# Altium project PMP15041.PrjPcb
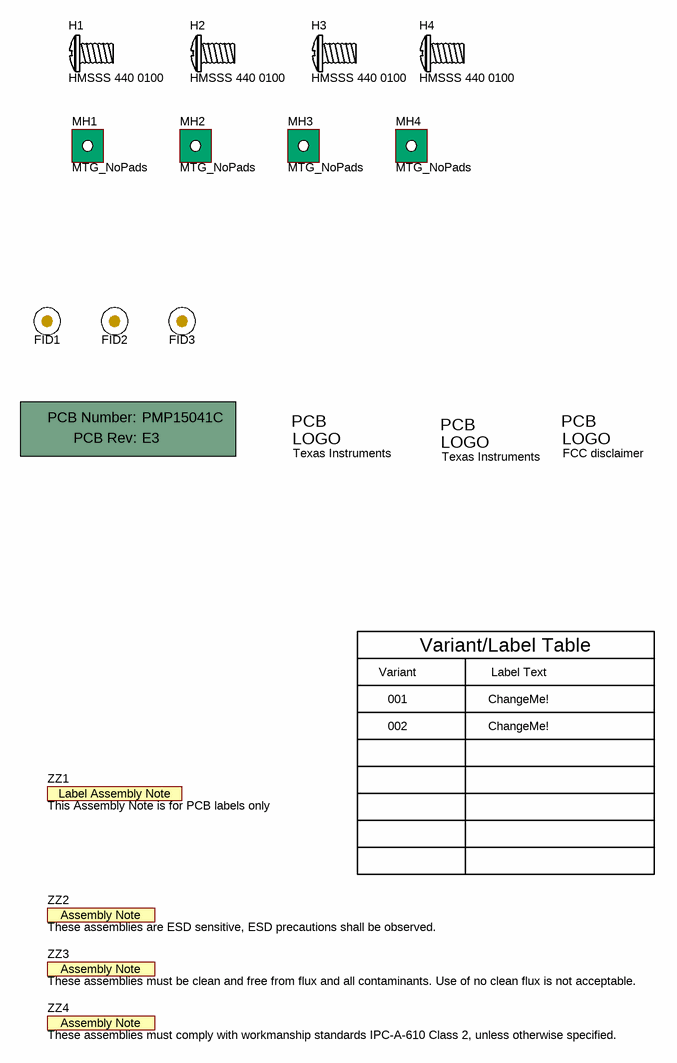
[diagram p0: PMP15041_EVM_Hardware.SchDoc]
CopyrightYear: 2017; PCB_Layout: K Nielson; PCB_Rev: E3; PRJ_Customer: Public Release; PRJ_Engineer: G Roecker; PRJ_Number: PMP15041C; PRJ_Title: LM5150/LM5141 APEC Demo; SCH_Rev: E3; TechSupport: http://www.ti.com/support; TID: N/A
4 sheets, 129 parts. Net scope: global (net labels, ports and power ports of the same name join across sheets).
Board file: PMP15041_EVM_PCB.PcbDoc
Sheets:
  PMP15041_EVM_Hardware.SchDoc
  PMP15041_EVM_Boost_Stage.SchDoc
  PMP15041_EVM_Buck_Stage.SchDoc
  PMP15041_SYNC_Stage.SchDoc

## Sheet PMP15041_EVM_Hardware.SchDoc
size 431 x 279 mm; Date: Not shown in title block; ApprovedBy: Not shown in title block; CheckedBy: Not shown in title block; Author: Not shown in title block; CompanyName: Not shown in title block; Engineer: Not shown in title block; Organization: Not shown in title block; Address1: Not shown in title block; Address2: Not shown in title block; Address3: Not shown in title block; Address4: Not shown in title block; DocumentNumber: 2; Revision: Use project parameter SCH_Rev; SheetNumber: 2; SheetTotal: 5; PageSetup: Record=PageOptions¦CenterHorizontal=True¦CenterVertical=True¦PrintScale=1.00¦XCorrection=1.00¦YCorrection=1.00¦PrintKind=0¦BorderSize=5000000¦LeftOffset=0¦BottomOffset=0¦Orientation=2¦PaperLength=1000¦PaperWidth=1000¦Scale=100¦PaperSource=15¦PrintQuality=600¦MediaType=1¦DitherType=10¦PaperKind=Letter¦PrintScaleMode=1

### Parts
!PCB1  Printed Circuit Board  (value not drawn)  (mechanical)
FID1  Fiducial  [Fiducial10-20]  (value not drawn)
FID2  Fiducial  [Fiducial10-20]  (value not drawn)
FID3  Fiducial  [Fiducial10-20]  (value not drawn)
H1  HMSSS 440 0100  (mechanical)
H2  HMSSS 440 0100  (mechanical)
H3  HMSSS 440 0100  (mechanical)
H4  HMSSS 440 0100  (mechanical)
Logo1  Texas Instruments  [TI_Stacked_Overlay_Small]  (no BOM)
Logo2  Texas Instruments  [TI_Symbol_Overlay_Medium]  (no BOM)
Logo3  FCC disclaimer  [FCC_disclaimer_stacked]  (no BOM)
MH1  MTG_NoPads  [MTG_159mil]  (no BOM)
MH2  MTG_NoPads  [MTG_159mil]  (no BOM)
MH3  MTG_NoPads  [MTG_159mil]  (no BOM)
MH4  MTG_NoPads  [MTG_159mil]  (no BOM)
ZZ1  This Assembly Note is for PCB labels only  [AssemblyNoteLabel]  (no BOM)
ZZ2  These assemblies are ESD sensitive, ESD precautions shall be observed.  [AssemblyNote]  (no BOM)
ZZ3  These assemblies must be clean and free from flux and all contaminants. Use of no clean flux is not acceptable.  [AssemblyNote]  (no BOM)
ZZ4  These assemblies must comply with workmanship standards IPC-A-610 Class 2, unless otherwise specified.  [AssemblyNote]  (no BOM)

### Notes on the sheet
- Variant
- Variant/Label Table
- Label Text
- 001
- 002
- ChangeMe!

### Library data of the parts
!PCB1 = CMP-0003618-2: Manufacturer: Any; PartNumber: PMP15041C
FID1-FID3 = CMP-0077181-1: Fiducial mark.  There is nothing to buy or mount.
H1-H4 = CMP-0003896-1: MACHINE SCREW HEX 4-40; Manufacturer: B&F Fastener Supply; CompType: Hardware
Logo1 = CMP-0074838-1: Texas Instrument Corporate Signature; SymbolCreator: a0412235; Lib Reference: TI_Logo; Library Reference: Logo
Logo2 = CMP-0074838-1: Texas Instrument Corporate Signature; Library Reference: Logo; SymbolCreator: a0412235; Lib Reference: TI_Logo
Logo3 = CMP-0074847-1: FCC_disclaimer; Library Reference: Logo
MH1-MH4 = CMP-0078424-2: PCB Mounting Hole, No Pad; Manufacturer: Any; Key: Mounting Hole (non-standard) No Pad
ZZ1 = CMP-0003616-3
ZZ2 = CMP-0077236-1
ZZ3 = CMP-0077237-1
ZZ4 = CMP-0077238-1

## Sheet PMP15041_EVM_Boost_Stage.SchDoc
size 431 x 279 mm; Date: Not shown in title block; ApprovedBy: Not shown in title block; CheckedBy: Not shown in title block; Author: Not shown in title block; CompanyName: Not shown in title block; Engineer: Not shown in title block; Organization: Not shown in title block; Address1: Not shown in title block; Address2: Not shown in title block; Address3: Not shown in title block; Address4: Not shown in title block; DocumentNumber: 3; Revision: Use project parameter SCH_Rev; SheetNumber: 3; SheetTotal: 5; PageSetup: Record=PageOptions¦CenterHorizontal=True¦CenterVertical=True¦PrintScale=1.00¦XCorrection=1.00¦YCorrection=1.00¦PrintKind=0¦BorderSize=5000000¦LeftOffset=0¦BottomOffset=0¦Orientation=2¦PaperLength=1000¦PaperWidth=1000¦Scale=100¦PaperSource=15¦PrintQuality=600¦MediaType=1¦DitherType=10¦PaperKind=Letter¦PrintScaleMode=1
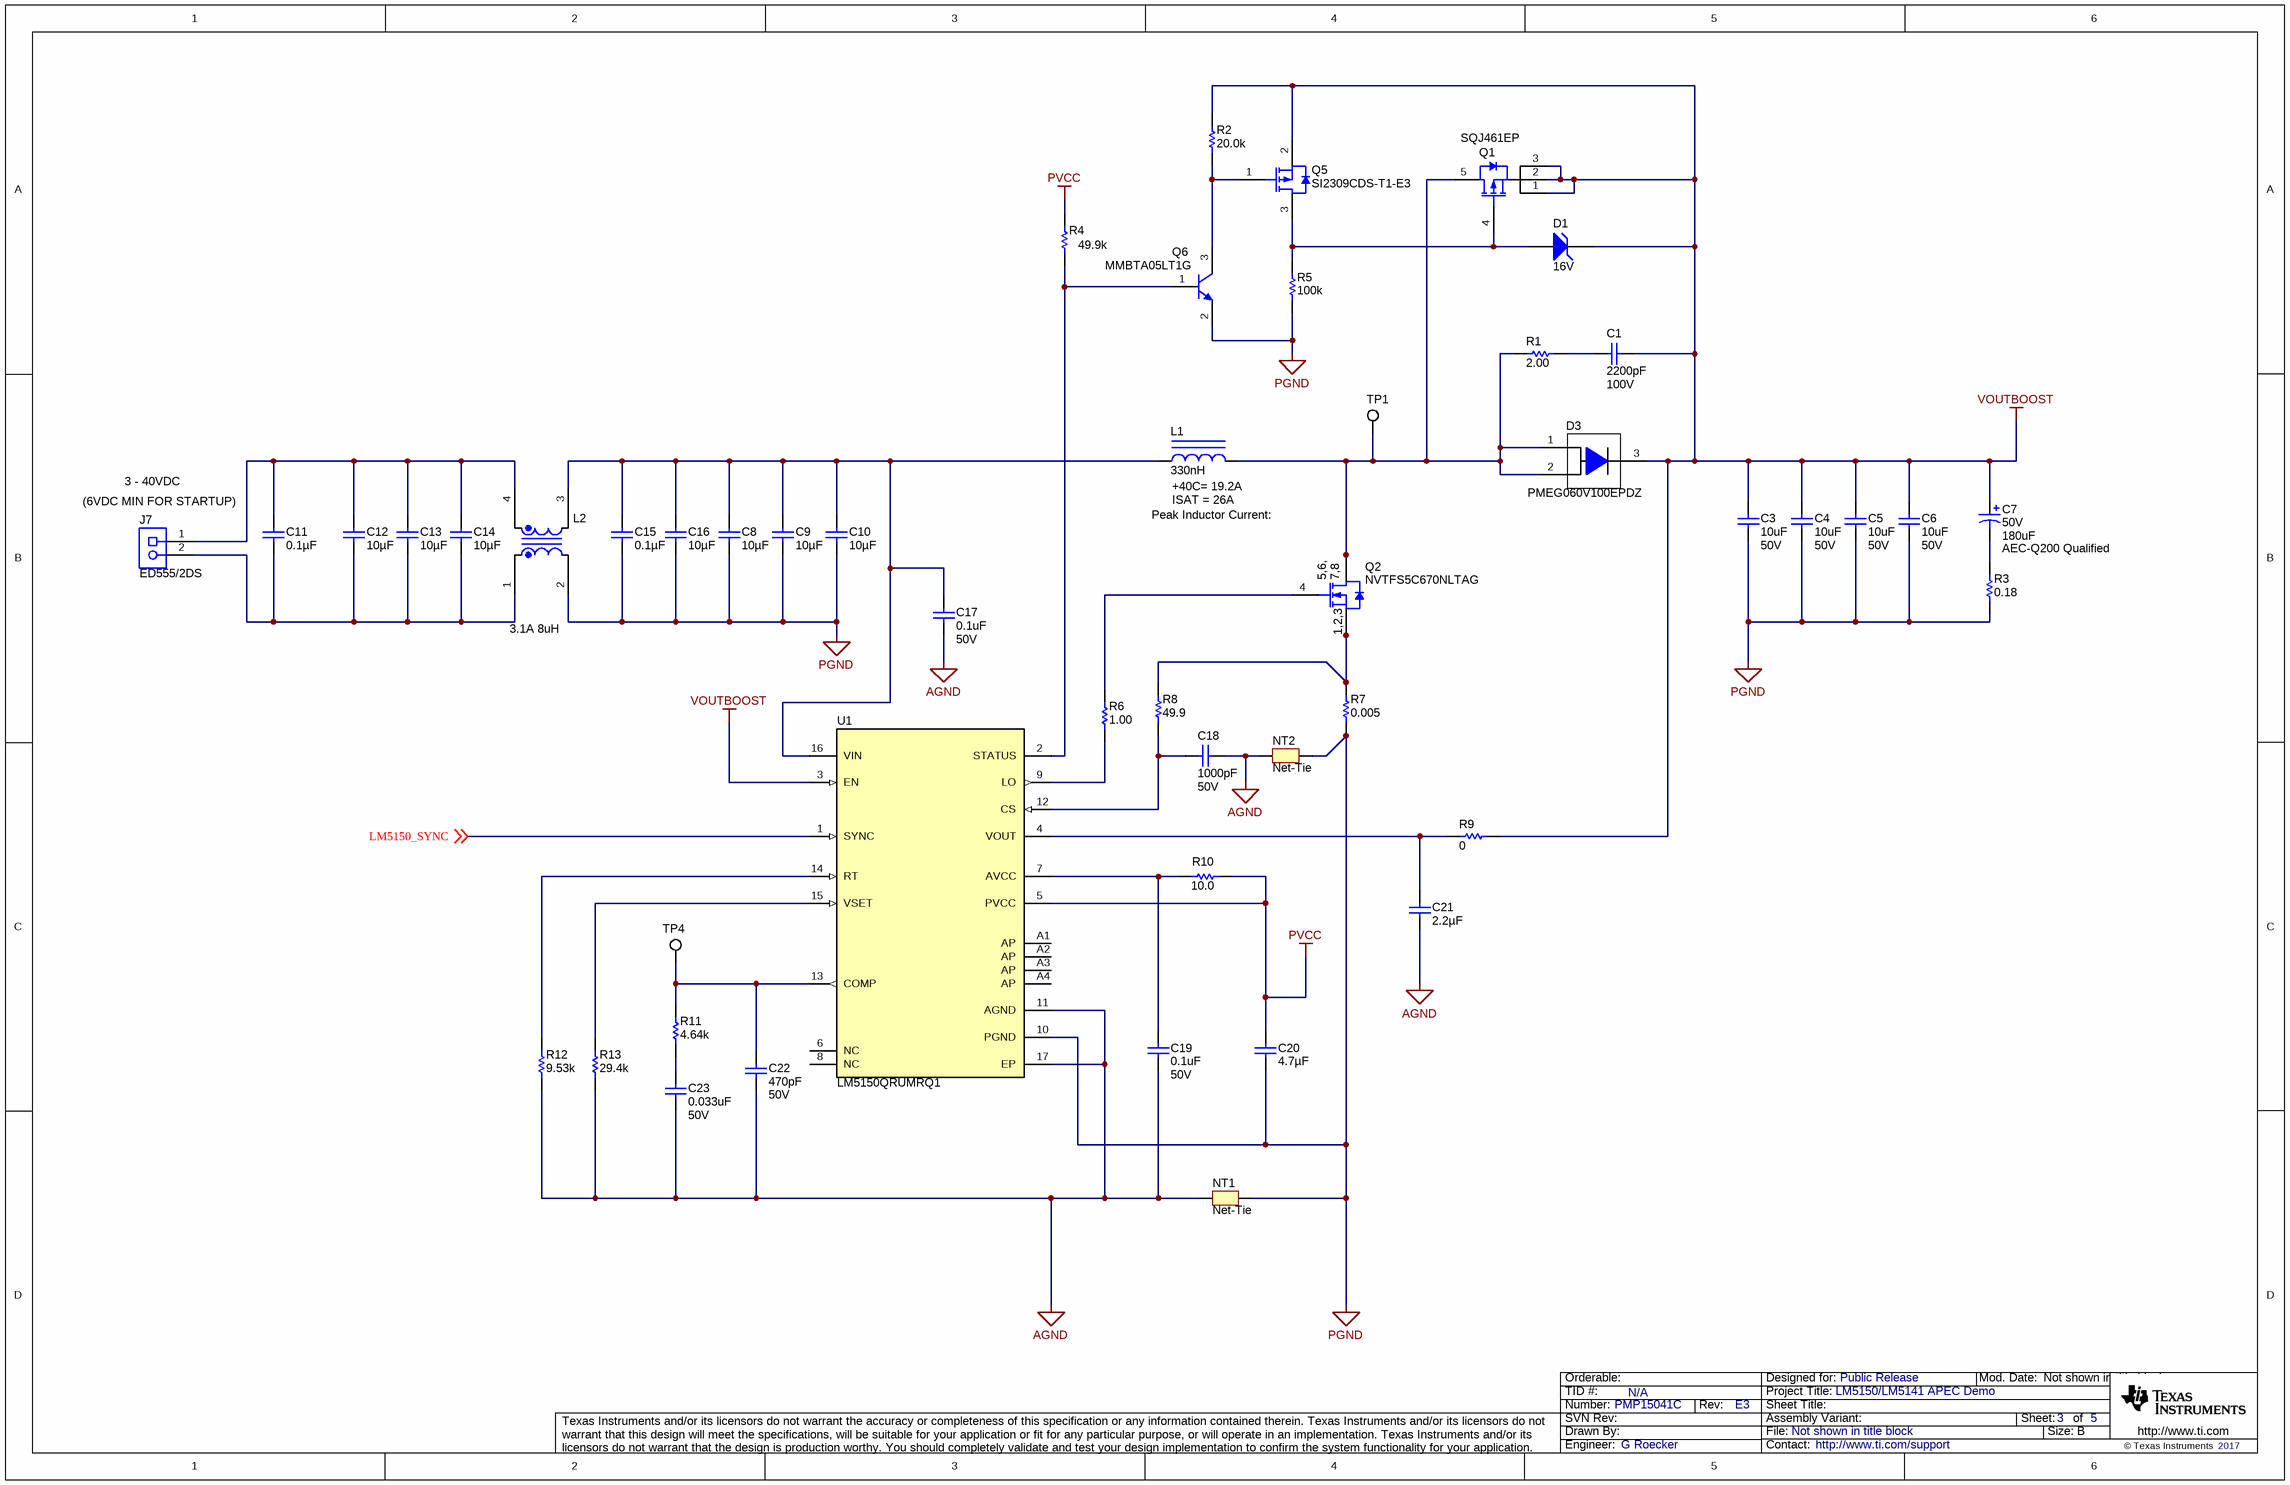
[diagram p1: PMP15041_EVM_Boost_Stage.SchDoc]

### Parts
C1  ValueDisplayed: 2200pF  VDC_V: 100V  [0603L]  (hidden comment: GRM188R72A222KA01D)
C3  ValueDisplayed: 10uF  VDC_V: 50V  [1210_280]  (hidden comment: CGA6P3X7S1H106K250AB)
C4  ValueDisplayed: 10uF  VDC_V: 50V  [1210_280]  (hidden comment: CGA6P3X7S1H106K250AB)
C5  ValueDisplayed: 10uF  VDC_V: 50V  [1210_280]  (hidden comment: CGA6P3X7S1H106K250AB)
C6  ValueDisplayed: 10uF  VDC_V: 50V  [1210_280]  (hidden comment: CGA6P3X7S1H106K250AB)
C7  VDC_V: 50V  ValueDisplayed: 180uF  [CR_1000x1270]  (hidden comment: PCR1H181MCL1GS)
C8  ValueDisplayed: 10µF  [1210_280]  (hidden comment: GRM32ER71H106KA12L)
C9  ValueDisplayed: 10µF  [1210_280]  (hidden comment: GRM32ER71H106KA12L)
C10  ValueDisplayed: 10µF  [1210_280]  (hidden comment: GRM32ER71H106KA12L)
C11  ValueDisplayed: 0.1µF  [0805_HV]  (hidden comment: C0805C104K1RACTU)
C12  ValueDisplayed: 10µF  [1210_280]  (hidden comment: C3225X7R1H106M250AC)
C13  ValueDisplayed: 10µF  [1210_280]  (hidden comment: C3225X7R1H106M250AC)
C14  ValueDisplayed: 10µF  [1210_280]  (hidden comment: C3225X7R1H106M250AC)
C15  ValueDisplayed: 0.1µF  [0805_HV]  (hidden comment: C0805C104K1RACTU)
C16  ValueDisplayed: 10µF  [1210_280]  (hidden comment: C3225X7R1H106M250AC)
C17  ValueDisplayed: 0.1uF  VDC_V: 50V  [0402L]  (hidden comment: CGA2B3X7R1H104M050BB)
C18  ValueDisplayed: 1000pF  VDC_V: 50V  [0402L]  (hidden comment: CGA2B2C0G1H102J050BA)
C19  ValueDisplayed: 0.1uF  VDC_V: 50V  [0402L]  (hidden comment: GCM155R71H104KE02D)
C20  ValueDisplayed: 4.7µF  [0805_HV1]  (hidden comment: GRM21BR71C475KA73L)
C21  ValueDisplayed: 2.2µF  [0805_HV1]  (hidden comment: C2012X7R1H225K125AC)
C22  ValueDisplayed: 470pF  VDC_V: 50V  [0402L]  (hidden comment: GCM155R71H471KA37D)
C23  ValueDisplayed: 0.033uF  VDC_V: 50V  [0402L]  (hidden comment: CGA2B3X7R1H333K050BB)
D1  value 16V  [SOD-123]  (hidden comment: DDZ16Q-7)
D3  PMEG060V100EPDZ  [SOT1289]
J7  ED555/2DS  [TERM_BLK_ED555-2DS]
L1  Isat: ISAT = 26A  Imax_A: +40C= 19.2A  ValueDisplayed: 330nH  [XAL5030]  (hidden comment: XAL5030-331MEB)
L2  PLT5BPH5013R1SNL  [PLT5BPH_SN]  (value not drawn)
NT1  Net-Tie  [Net-Tie_10mil]  (net tie, no BOM)
NT2  Net-Tie  [Net-Tie_10mil]  (net tie, no BOM)
Q1  SQJ461EP  [PowerPAK_SO-8L]
Q2  NVTFS5C670NLTAG  [Power_WDFN-8]
Q5  SI2309CDS-T1-E3  [SOT-23]
Q6  MMBTA05LT1G  [SOT-23]
R1  ValueDisplayed: 2.00  [1210M]  (hidden comment: ERJ-14BQF2R0U)
R2  ValueDisplayed: 20.0k  [0603L]  (hidden comment: CRCW060320K0FKEA)
R3  ValueDisplayed: 0.18  [1206]  (hidden comment: ERJ-8RSJR18V)
R4  ValueDisplayed: 49.9k  [0603L]  (hidden comment: CRCW060349K9FKEA)
R5  ValueDisplayed: 100k  [0603L]  (hidden comment: CRCW0603100KFKEA)
R6  ValueDisplayed: 1.00  [0402L]  (hidden comment: CRCW04021R00FKED)
R7  ValueDisplayed: 0.005  [KRL2012]  (hidden comment: KRL2012M-R005-F-T1)
R8  ValueDisplayed: 49.9  [0402L]  (hidden comment: CRCW040249R9FKED)
R9  ValueDisplayed: 0  [0402L]  (hidden comment: MCR01MZPJ000)
R10  ValueDisplayed: 10.0  [0402L]  (hidden comment: RMCF0402JT10R0)
R11  ValueDisplayed: 4.64k  [0402L]  (hidden comment: CRCW04024K64FKED)
R12  ValueDisplayed: 9.53k  [0402L]  (hidden comment: CRCW04029K53FKED)
R13  ValueDisplayed: 29.4k  [0402L]  (hidden comment: CRCW040229K4FKED)
TP1  5015  [Testpoint_Keystone_Miniature]  (value not drawn)
TP4  5002  [Keystone5002]  (value not drawn)
U1  LM5150QRUMRQ1  [RUM0016C]

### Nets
AGND: C17.2 C18.2 C19.1 C21.1 C22.2 C23.2 NT1.1 NT2.1 R12.1 R13.1 U1.11(AGND) U1.17(EP)
PGND: C3.2 C4.2 C5.2 C6.2 C8.2 C9.2 C10.2 C15.2 C16.2 C20.2 L2.2 NT1.2 NT2.2 Q6.2(E) R3.1 R5.1 R7.1 U1.10(PGND)
PVCC: C20.1 R4.2 R10.2 U1.5(PVCC)
VOUTBOOST: C1.1 C3.1 C4.1 C5.1 C6.1 C7.1(+) D1.1(K) D3.3(K) Q1.1(S) Q1.2(S) Q1.3(S) Q5.2(S) R2.2 R9.1 U1.3(EN)
LM5150_SYNC: U1.1(SYNC) ; off-sheet LM5150_SYNC
NetC1_2: C1.2 R1.2
NetC7_2: C7.2(-) R3.2
NetC8_1: C8.1 C9.1 C10.1 C15.1 C16.1 C17.1 L1.1 L2.3 U1.16(VIN)
NetC11_1: C11.1 C12.1 C13.1 C14.1 J7.1 L2.4
NetC11_2: C11.2 C12.2 C13.2 C14.2 J7.2 L2.1
NetC18_1: C18.1 R8.1 U1.12(CS)
NetC19_2: C19.2 R10.1 U1.7(AVCC)
NetC21_2: C21.2 R9.2 U1.4(VOUT)
NetC22_1: C22.1 R11.2 TP4.1 U1.13(COMP)
NetC23_1: C23.1 R11.1
NetD1_2: D1.2(A) Q1.4(G) Q5.3(D) R5.2
NetD3_1: D3.1(A) D3.2(A) L1.2 Q1.5(D) Q2.5(D) Q2.6(D) Q2.7(D) Q2.8(D) Q2.9(D) R1.1 TP1.1
NetQ2_1: Q2.1(S) Q2.2(S) Q2.3(S) R7.2 R8.2
NetQ2_4: Q2.4(G) R6.1
NetQ5_1: Q5.1(G) Q6.3(C) R2.1
NetQ6_1: Q6.1(B) R4.1 U1.2(STATUS)
NetR6_2: R6.2 U1.9(LO)
NetR12_2: R12.2 U1.14(RT)
NetR13_2: R13.2 U1.15(VSET)

Not connected (* = marked no-connect by the designer): U1 6(NC) 8(NC) A1(AP) A2(AP) A3(AP) A4(AP)

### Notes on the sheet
- 3 - 40VDC
- (6VDC MIN FOR STARTUP)
- Peak Inductor Current:
- AEC-Q200 Qualified
- 3.1A 8uH

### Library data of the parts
C1 = CMP-0007475-4: CAP, CERM, 2200 pF, 100 V, +/- 10%, X7R, 0603; Manufacturer: MuRata; Polarized: N; CompType: Capacitor; Value: 2200pF; U/M: EA; Cap_F: 2.2nF; Value1: Unknown; TaMin_C: -55°C; TaMax_C: 125°C; Cap_Case: 0603; SizeArea_mm2: 1.28; SizeAreaWB_mm2: 4.68; SizeX_mm: 1.6; SizeY_mm: 0.8; SizeZ_mm: 1; AEC Category: Q200
C3 C5 = CMP-0009164-2: CAP, CERM, 10 uF, 50 V, +/- 10%, X7S, AEC-Q200 Grade 1, 1210; Manufacturer: TDK; Polarized: N; CompType: Capacitor; Value: 10uF; U/M: EA; Cap_F: 10µF; ESR_ohm: 2.827m; Value1: 0.002827 ohm; IRMS_A: 4.37286A; TaMin_C: -55°C; TaMax_C: 125°C; SizeArea_mm2: 8; SizeAreaWB_mm2: 14.7; SizeX_mm: 3.2; SizeY_mm: 2.5; SizeZ_mm: 2.8; AEC Category: Q200; AEC Qualified: Y; AEC Grade: 1
C4 C6 = CMP-0009164-2: CAP, CERM, 10 uF, 50 V, +/- 10%, X7S, AEC-Q200 Grade 1, 1210; Manufacturer: TDK; Polarized: N; Value: 10uF; U/M: EA; Cap_F: 10µF; ESR_ohm: 2.827m; Value1: 0.002827 ohm; IRMS_A: 4.37286A; TaMin_C: -55°C; TaMax_C: 125°C; SizeArea_mm2: 8; SizeAreaWB_mm2: 14.7; SizeX_mm: 3.2; SizeY_mm: 2.5; SizeZ_mm: 2.8; AEC Category: Q200; AEC Qualified: Y; AEC Grade: 1
C7 = CMP-0012273-3: CAP, Aluminum Polymer, 180 uF, 50 V, +/- 20%, 0.019 ohm, SMD, 2-Leads, Dia 10.5mm, Pin Spacing 8mm SMD; Manufacturer: Nichicon; TaMin_C: -55°C; ESR_ohm: 0.019; Polarized: Y; Value: 180uF; TaMax_C: 125°C; Cap_Case: 10x12.7mm; CompType: Capacitor; AEC Qualified: N; Cap_F: 180µF; IRMS_A: 3.5A; AEC Category: Q200
C8-C10 = GRM32ER71H106KA12L: CAP, CERM, 10 µF, 50 V, +/- 10%, X7R, 1210; Manufacturer: MuRata; Polarized: N; CompType: Capacitor; Value: 10uF; U/M: EA; Cap_F: 0.00001; Tolerance_%: 10; Value1: Unknown; VDC_V: 50; Value2: 50V; TaMin_C: -55; TaMax_C: 125; Cap_Case: 1210; SizeArea_mm2: 8; SizeAreaWB_mm2: 14.7; SizeX_mm: 3.2; SizeY_mm: 2.5; SizeZ_mm: 2.7; AEC Category: Q200
C11 C15 = C0805C104K1RACTU: CAP, CERM, 0.1 µF, 100 V, +/- 10%, X7R, 0805; Manufacturer: Kemet; Polarized: N; CompType: Capacitor; Value: 0.1uF; U/M: EA; Cap_F: 0.0000001; Tolerance_%: 10; ESR_ohm: 0.064; Value1: 0.064 ohm; VDC_V: 100; Value2: 100V; IRMS_A: 1.64; TaMin_C: -55; TaMax_C: 125; Cap_Case: 0805
C12-C14 C16 = C3225X7R1H106M250AC: CAP, CERM, 10 µF, 50 V, +/- 20%, X7R, 1210; Manufacturer: TDK; Polarized: N; CompType: Capacitor; Value: 10uF; U/M: EA; Cap_F: 0.00001; Tolerance_%: 20; Value1: Unknown; VDC_V: 50; Value2: 50V; TaMin_C: -55; TaMax_C: 125; Cap_Case: 1210
C17 = CMP-0006326-2: CAP, CERM, 0.1 uF, 50 V, +/- 20%, X7R, AEC-Q200 Grade 1, 0402; Manufacturer: TDK; Polarized: N; Value: 0.1uF; U/M: EA; Cap_F: 100nF; Value1: Unknown; TaMin_C: -55°C; TaMax_C: 125°C; Cap_Case: 0402; SizeArea_mm2: 0.5; SizeAreaWB_mm2: 3; SizeX_mm: 1; SizeZ_mm: 0.6; AEC Category: Q200; AEC Qualified: Y
C18 = CMP-0006309-2: CAP, CERM, 1000 pF, 50 V, +/- 5%, C0G/NP0, AEC-Q200 Grade 1, 0402; Manufacturer: TDK; Polarized: N; Value: 1000pF; U/M: EA; Cap_F: 1nF; Value1: Unknown; TaMin_C: -55°C; TaMax_C: 125°C; Cap_Case: 0402; SizeArea_mm2: 0.5; SizeAreaWB_mm2: 3; SizeX_mm: 1; SizeZ_mm: 0.6; AEC Category: Q200; AEC Qualified: Y
C19 = CMP-0006356-2: CAP, CERM, 0.1 uF, 50 V, +/- 10%, X7R, AEC-Q200 Grade 1, 0402; Manufacturer: MuRata; Polarized: N; Value: 0.1uF; U/M: EA; Cap_F: 100nF; Value1: Unknown; TaMin_C: -55°C; TaMax_C: 125°C; Cap_Case: 0402; SizeArea_mm2: 0.5; SizeAreaWB_mm2: 3; SizeX_mm: 1; SizeZ_mm: 0.6; AEC Category: Q200; AEC Qualified: Y
C20 = GRM21BR71C475KA73L: CAP, CERM, 4.7 µF, 16 V, +/- 10%, X7R, 0805; Manufacturer: MuRata; Polarized: N; CompType: Capacitor; Value: 4.7uF; U/M: EA; Cap_F: 0.0000047; Tolerance_%: 10; ESR_ohm: 0.006; Value1: 0.006 ohm; VDC_V: 16; Value2: 16V; TaMin_C: -55; TaMax_C: 125; Cap_Case: 0805; SizeArea_mm2: 2.5; SizeAreaWB_mm2: 6.75; SizeX_mm: 2; SizeY_mm: 1.25; SizeZ_mm: 1.45; AEC Category: Q200
C21 = C2012X7R1H225K125AC: CAP, CERM, 2.2 µF, 50 V, +/- 10%, X7R, 0805; Manufacturer: TDK; Polarized: N; CompType: Capacitor; Value: 2.2uF; U/M: EA; Cap_F: 0.0000022; Tolerance_%: 10; ESR_ohm: 0.00366; Value1: 0.00366 ohm; VDC_V: 50; Value2: 50V; IRMS_A: 3.41207; TaMin_C: -55; TaMax_C: 125; Cap_Case: 0805; SizeArea_mm2: 2.5; SizeAreaWB_mm2: 6.75; SizeX_mm: 2; SizeY_mm: 1.25; SizeZ_mm: 1.45; AEC Category: Q200
C22 = CMP-0006360-2: CAP, CERM, 470 pF, 50 V, +/- 10%, X7R, AEC-Q200 Grade 1, 0402; Manufacturer: MuRata; Polarized: N; CompType: Capacitor; Value: 470pF; U/M: EA; Value1: Unknown; TaMin_C: -55°C; TaMax_C: 125°C; Cap_Case: 0402; SizeArea_mm2: 0.5; SizeAreaWB_mm2: 3; SizeX_mm: 1; SizeZ_mm: 0.6; AEC Category: Q200; AEC Qualified: Y
C23 = CMP-0006329-2: CAP, CERM, 0.033 uF, 50 V, +/- 10%, X7R, AEC-Q200 Grade 1, 0402; Manufacturer: TDK; Polarized: N; U/M: EA; Cap_F: 33nF; ESR_ohm: 0.098477; Value1: 0.098477 ohm; IRMS_A: 5.3078dA; TaMin_C: -55°C; TaMax_C: 125°C; Cap_Case: 0402; SizeArea_mm2: 0.5; SizeAreaWB_mm2: 3; SizeX_mm: 1; SizeZ_mm: 0.6; AEC Category: Q200; AEC Qualified: Y
D1 = DDZ6V2B-7: Diode, Zener, 6.2 V, 500 mW, AEC-Q101, SOD-123; Manufacturer: Diodes Inc.; SymbolCreator: a0412235; U/M: EA; Power_W: 0.5; Vz_V: 6.2; Value1: 0.5W; RJA_CperW: 305; AEC Category: Q101; AEC Qualified: Y; SizeAreaWB_mm2: 13.095; SizeArea_mm2: 6.545; SizeX_mm: 3.85; SizeY_mm: 1.7; SizeZ_mm: 1.35
D3 = CMP-0028984-1: Diode, Schottky, 60 V, 10 A, AEC-Q101, CFP15; Manufacturer: Nexperia; Io_A: 10A; SizeAreaWB_mm2: 53.55; Vr_V: 60V; TJmax_C: 175°C; U/M: EA; Value: 60V; SizeZ_mm: 0.82; SizeX_mm: 6.5; SizeY_mm: 4.3; Vf_V: 5.6dV; Value2: 0.56V; SizeArea_mm2: 27.95; AEC Qualified: Y; AEC Category: Q101
J7 = CMP-0074913-1: Terminal Block, 3.5mm Pitch, 2x1, TH; Manufacturer: On-Shore Technology; Cert_VDE: Y; CNHeader: False; Current_A: 6A; Green_Lifecycle: Active; Shrouded: N; Gender: Female; Green_REACh: Passed; Voltage_V: 150V; Row_Count: 1; Pitch_mm: 3.5; ContactFinish: Brass; CT: True
L1 = CMP-0061002-1: Inductor, Shielded, Composite, 330 nH, 19.2 A, 0.0032 ohm, SMD; Manufacturer: Coilcraft; Irms: 19.2A @ 40C rise; SizeAreaWB_mm2: 54.4544; DCR_ohm: 3.2m; Value: 330nH; SizeZ_mm: 3.1; SizeX_mm: 5.28; SizeY_mm: 5.48; Value2: 19.2A; SizeArea_mm2: 28.9344; AEC Category: Q200; Green_Lifecycle: Not Set; Green_REACh: Incomplete
L2 = CMP-0013206-2: Coupled inductor,  A, 0.017 ohm, SMD; Manufacturer: MuRata; SizeAreaWB_mm2: 58.1; DCR_ohm: 0.017; SizeZ_mm: 5; SizeY_mm: 6.3; SizeArea_mm2: 31.5
NT1 NT2 = Net-Tie: Single point connection between nets.; SymbolCreator: codlsc
Q1 = CMP-0000140-2: MOSFET, P-CH, -60 V, -30 A, PowerPAK_SO-8L; Manufacturer: Vishay-Siliconix; Alternate Manufacturer: None; U/M: EA; VdsMax_V: -60V; SizeZ_mm: 1.14; ChType: P; Value2: 90 nC; Value1: 0.03; SizeX_mm: 6.15; SizeY_mm: 5.13; Vgs_V: -20V; Value: -60V; Rdson45_ohm: 0.031; SizeArea_mm2: 31.5495; AEC Category: Q101; IdsMax_A: -30A; SizeAreaWB_mm2: 58.1095; QgTyp_nC: 90
Q2 = NVTFS5C670NLWFTAG: MOSFET N-CH 60V 16A 70A 8WDFN; Manufacturer: Used in BOM report; SymbolVersion: use current date i.e. 2008-05-20; SymbolCreator: Use a-id; CompType: FET; U/M: EA, IN, or GM
Q5 = CMP-0000090-2: MOSFET, P-CH, -60 V, -1.6 A, SOT-23; Alternate Manufacturer: None; Manufacturer: Vishay-Siliconix; SizeZ_mm: 1.1; ChType: P; Value2: 2.7 nC; Value1: 0.4; VdsMax_V: -60V; SizeX_mm: 2.5; SizeY_mm: 3; Vgs_V: -20V; Value: -60V; Rdson45_ohm: 4.5d; SizeArea_mm2: 7.5; AEC Category: Q101; IdsMax_A: -1.6A; SizeAreaWB_mm2: 14; U/M: EA; QgTyp_nC: 2.7
Q6 = CMP-0000488-2: Transistor, NPN, 60 V, 0.5 A, AEC-Q101, SOT-23; Manufacturer: ON Semiconductor; TaMax_C: 150°C; Value1: 0.5 A; Vcesat1_V: 2.5dV; SizeX_mm: 2.5; SizeY_mm: 3; TaMin_C: -55°C; IcRated_A: 5dA; CompType: BJT; SizeZ_mm: 1.1; AEC Qualified: Y; Value: 60 V; SizeArea_mm2: 7.5; NPN: 1; Vceo_V: 60V; PNP: 0; AEC Category: Q101; SizeAreaWB_mm2: 14; U/M: EA
R1 = ERJ-14BQF2R0U: RES, 2.00, 1%, 0.5 W, AEC-Q200 Grade 0, 1210; Manufacturer: Panasonic; CompType: Resistor; Value: 2.00; Res_ohm: 2; Value_Code: 2R00; Tolerance_%: 1; Power_W: 0.5; Value2: 0.5W; TempCo: 100 ppm/C; SizeArea_mm2: 8; SizeX_mm: 3.2; SizeY_mm: 2.5; SizeZ_mm: 1.35; EIA_Code: E96; U/M: EA; AEC Category: Q200; AEC Qualified: Y; AEC Grade: 0; SizeAreaWB_mm2: 14.7
R2 = CMP-0022204-4: RES, 20.0 k, 1%, 0.1 W, AEC-Q200 Grade 0, 0603; Manufacturer: Vishay-Dale; Power_W: 100mW; TempCo: 100 ppm/C; Value_Code: 20k0; Value: 20.0k; EIA_Code: E96; Res_ohm: 20k; SizeX_mm: 1.6; SizeY_mm: 0.8; SizeZ_mm: 1; Value2: 0.1W; SizeArea_mm2: 1.28; CompType: Resistor; AEC Qualified: Y; VDC_V: 75V; AEC Category: Q200; AEC Grade: 0
R3 = CMP-0018752-2: RES, 0.18, 5%, 0.25 W, 1206; Manufacturer: Panasonic; Power_W: 250mW; TempCo: 250 ppm/C; Value_Code: R180; U/M: EA; Value: 0.18; EIA_Code: E24; Res_ohm: 1.8d; SizeX_mm: 3.2; SizeY_mm: 1.6; SizeZ_mm: 1.35; Value2: 0.25W; SizeArea_mm2: 5.12; AEC Category: Q200
R4 = CMP-0022447-4: RES, 49.9 k, 1%, 0.1 W, AEC-Q200 Grade 0, 0603; Manufacturer: Vishay-Dale; Power_W: 100mW; TempCo: 100 ppm/C; Value_Code: 49k9; Value: 49.9k; EIA_Code: E96; SizeX_mm: 1.6; SizeY_mm: 0.8; SizeZ_mm: 1; Value2: 0.1W; SizeArea_mm2: 1.28; CompType: Resistor; AEC Qualified: Y; VDC_V: 75V; AEC Category: Q200; AEC Grade: 0
R5 = CMP-0021990-4: RES, 100 k, 1%, 0.1 W, AEC-Q200 Grade 0, 0603; Manufacturer: Vishay-Dale; Power_W: 100mW; TempCo: 100 ppm/C; Value: 100k; EIA_Code: E96; SizeX_mm: 1.6; SizeY_mm: 0.8; SizeZ_mm: 1; Value2: 0.1W; SizeArea_mm2: 1.28; CompType: Resistor; AEC Qualified: Y; VDC_V: 75V; AEC Category: Q200; AEC Grade: 0
R6 = CMP-0026129-1: RES, 1.00, 1%, 0.063 W, 0402; Manufacturer: Vishay-Dale; CompType: Resistor; Value: 1.00; Res_ohm: 1; Value_Code: 1R00; Power_W: 63mW; Value2: 0.063W; VDC_V: 50V; TempCo: 100 ppm/C; SizeArea_mm2: 0.5; SizeZ_mm: 0.6; EIA_Code: E96; U/M: EA; AEC Category: Q200
R7 = CMP-0015100-2: RES, 0.005, 1%, 1 W, AEC-Q200 Grade 0, 0508; Manufacturer: Susumu Co Ltd; Power_W: 1W; TempCo: 25 ppm/C; Value_Code: 5L000; U/M: EA; Value: 0.005; EIA_Code: E96; Res_ohm: 5m; CompType: Resistor; AEC Qualified: Y; AEC Grade: 0; AEC Category: Q200
R8 = CMP-0026404-1: RES, 49.9, 1%, 0.063 W, 0402; Manufacturer: Vishay-Dale; CompType: Resistor; Value: 49.9; Value_Code: 49R9; Power_W: 63mW; Value2: 0.063W; VDC_V: 50V; TempCo: 100 ppm/C; SizeArea_mm2: 0.5; SizeX_mm: 1; SizeZ_mm: 0.6; EIA_Code: E96; U/M: EA; AEC Category: Q200
R9 = CMP-0027002-2: RES, 0, 5%, 0.063 W, 0402; Manufacturer: Rohm; Value: 0; Value_Code: 0000; Power_W: 63mW; Value2: 0.063W; VDC_V: 50V; TempCo: 500 ppm/C; SizeArea_mm2: 0.5; SizeX_mm: 1; SizeZ_mm: 0.6; EIA_Code: E24; U/M: EA; AEC Category: Q200
R10 = CMP-0026764-1: RES, 10.0, 1%, 0.063 W, AEC-Q200 Grade 0, 0402; Manufacturer: Stackpole Electronics Inc; Value: 10.0; Res_ohm: 10; Value_Code: 10R0; Power_W: 63mW; Value2: 0.063W; TempCo: 100 ppm/C; SizeArea_mm2: 0.5; SizeX_mm: 1; SizeZ_mm: 0.6; EIA_Code: E96; U/M: EA; AEC Category: Q200; AEC Qualified: Y; AEC Grade: 0
R11 = CMP-0026411-1: RES, 4.64 k, 1%, 0.063 W, 0402; Manufacturer: Vishay-Dale; CompType: Resistor; Value: 4.64k; Value_Code: 4k64; Power_W: 63mW; Value2: 0.063W; VDC_V: 50V; TempCo: 100 ppm/C; SizeArea_mm2: 0.5; SizeX_mm: 1; SizeZ_mm: 0.6; EIA_Code: E96; U/M: EA; AEC Category: Q200
R12 = CMP-0026621-1: RES, 9.53 k, 1%, 0.063 W, 0402; Manufacturer: Vishay-Dale; CompType: Resistor; Value: 9.53k; Value_Code: 9k53; Power_W: 63mW; Value2: 0.063W; VDC_V: 50V; TempCo: 100 ppm/C; SizeArea_mm2: 0.5; SizeX_mm: 1; SizeZ_mm: 0.6; EIA_Code: E96; U/M: EA; AEC Category: Q200
R13 = CMP-0026225-1: RES, 29.4 k, 1%, 0.063 W, 0402; Manufacturer: Vishay-Dale; CompType: Resistor; Value: 29.4k; Value_Code: 29k4; Power_W: 63mW; Value2: 0.063W; VDC_V: 50V; TempCo: 100 ppm/C; SizeArea_mm2: 0.5; SizeX_mm: 1; SizeZ_mm: 0.6; EIA_Code: E96; U/M: EA; AEC Category: Q200
TP1 = 5015: Test Point, Miniature, SMT; Manufacturer: Keystone; CompType: Test Point Loop; Green_Lifecycle: Active; Green_REACh: Passed
TP4 = 5002: Test Point, Miniature, White, TH; Manufacturer: Keystone; CompType: Test Point Loop; ContactFinish: Silver
U1 = CMP-0014055-4: Wide VIN Automotive Low IQ Boost Controller, RUM0016C (WQFN-16); Alternate PartNumber: LM5150QRUMTQ1; Alternate Manufacturer: Texas Instruments; SizeAreaWB_mm2: 25; SizeZ_mm: 0.8; SizeX_mm: 4; SizeArea_mm2: 16; CompType: IC; AEC Qualified: Y; AEC Category: Q200

## Sheet PMP15041_EVM_Buck_Stage.SchDoc: LM5141 BUCK REGULATOR EVM
size 431 x 279 mm; Date: Not shown in title block; ApprovedBy: Not shown in title block; CheckedBy: Not shown in title block; Author: Not shown in title block; CompanyName: Not shown in title block; Engineer: Not shown in title block; Organization: Not shown in title block; Address1: Not shown in title block; Address2: Not shown in title block; Address3: Not shown in title block; Address4: Not shown in title block; DocumentNumber: 4; Revision: Use project parameter SCH_Rev; SheetNumber: 4; SheetTotal: 5; PageSetup: Record=PageOptions¦CenterHorizontal=True¦CenterVertical=True¦PrintScale=1.00¦XCorrection=1.00¦YCorrection=1.00¦PrintKind=0¦BorderSize=5000000¦LeftOffset=0¦BottomOffset=0¦Orientation=2¦PaperLength=1000¦PaperWidth=1000¦Scale=100¦PaperSource=15¦PrintQuality=600¦MediaType=1¦DitherType=10¦PaperKind=Letter¦PrintScaleMode=1
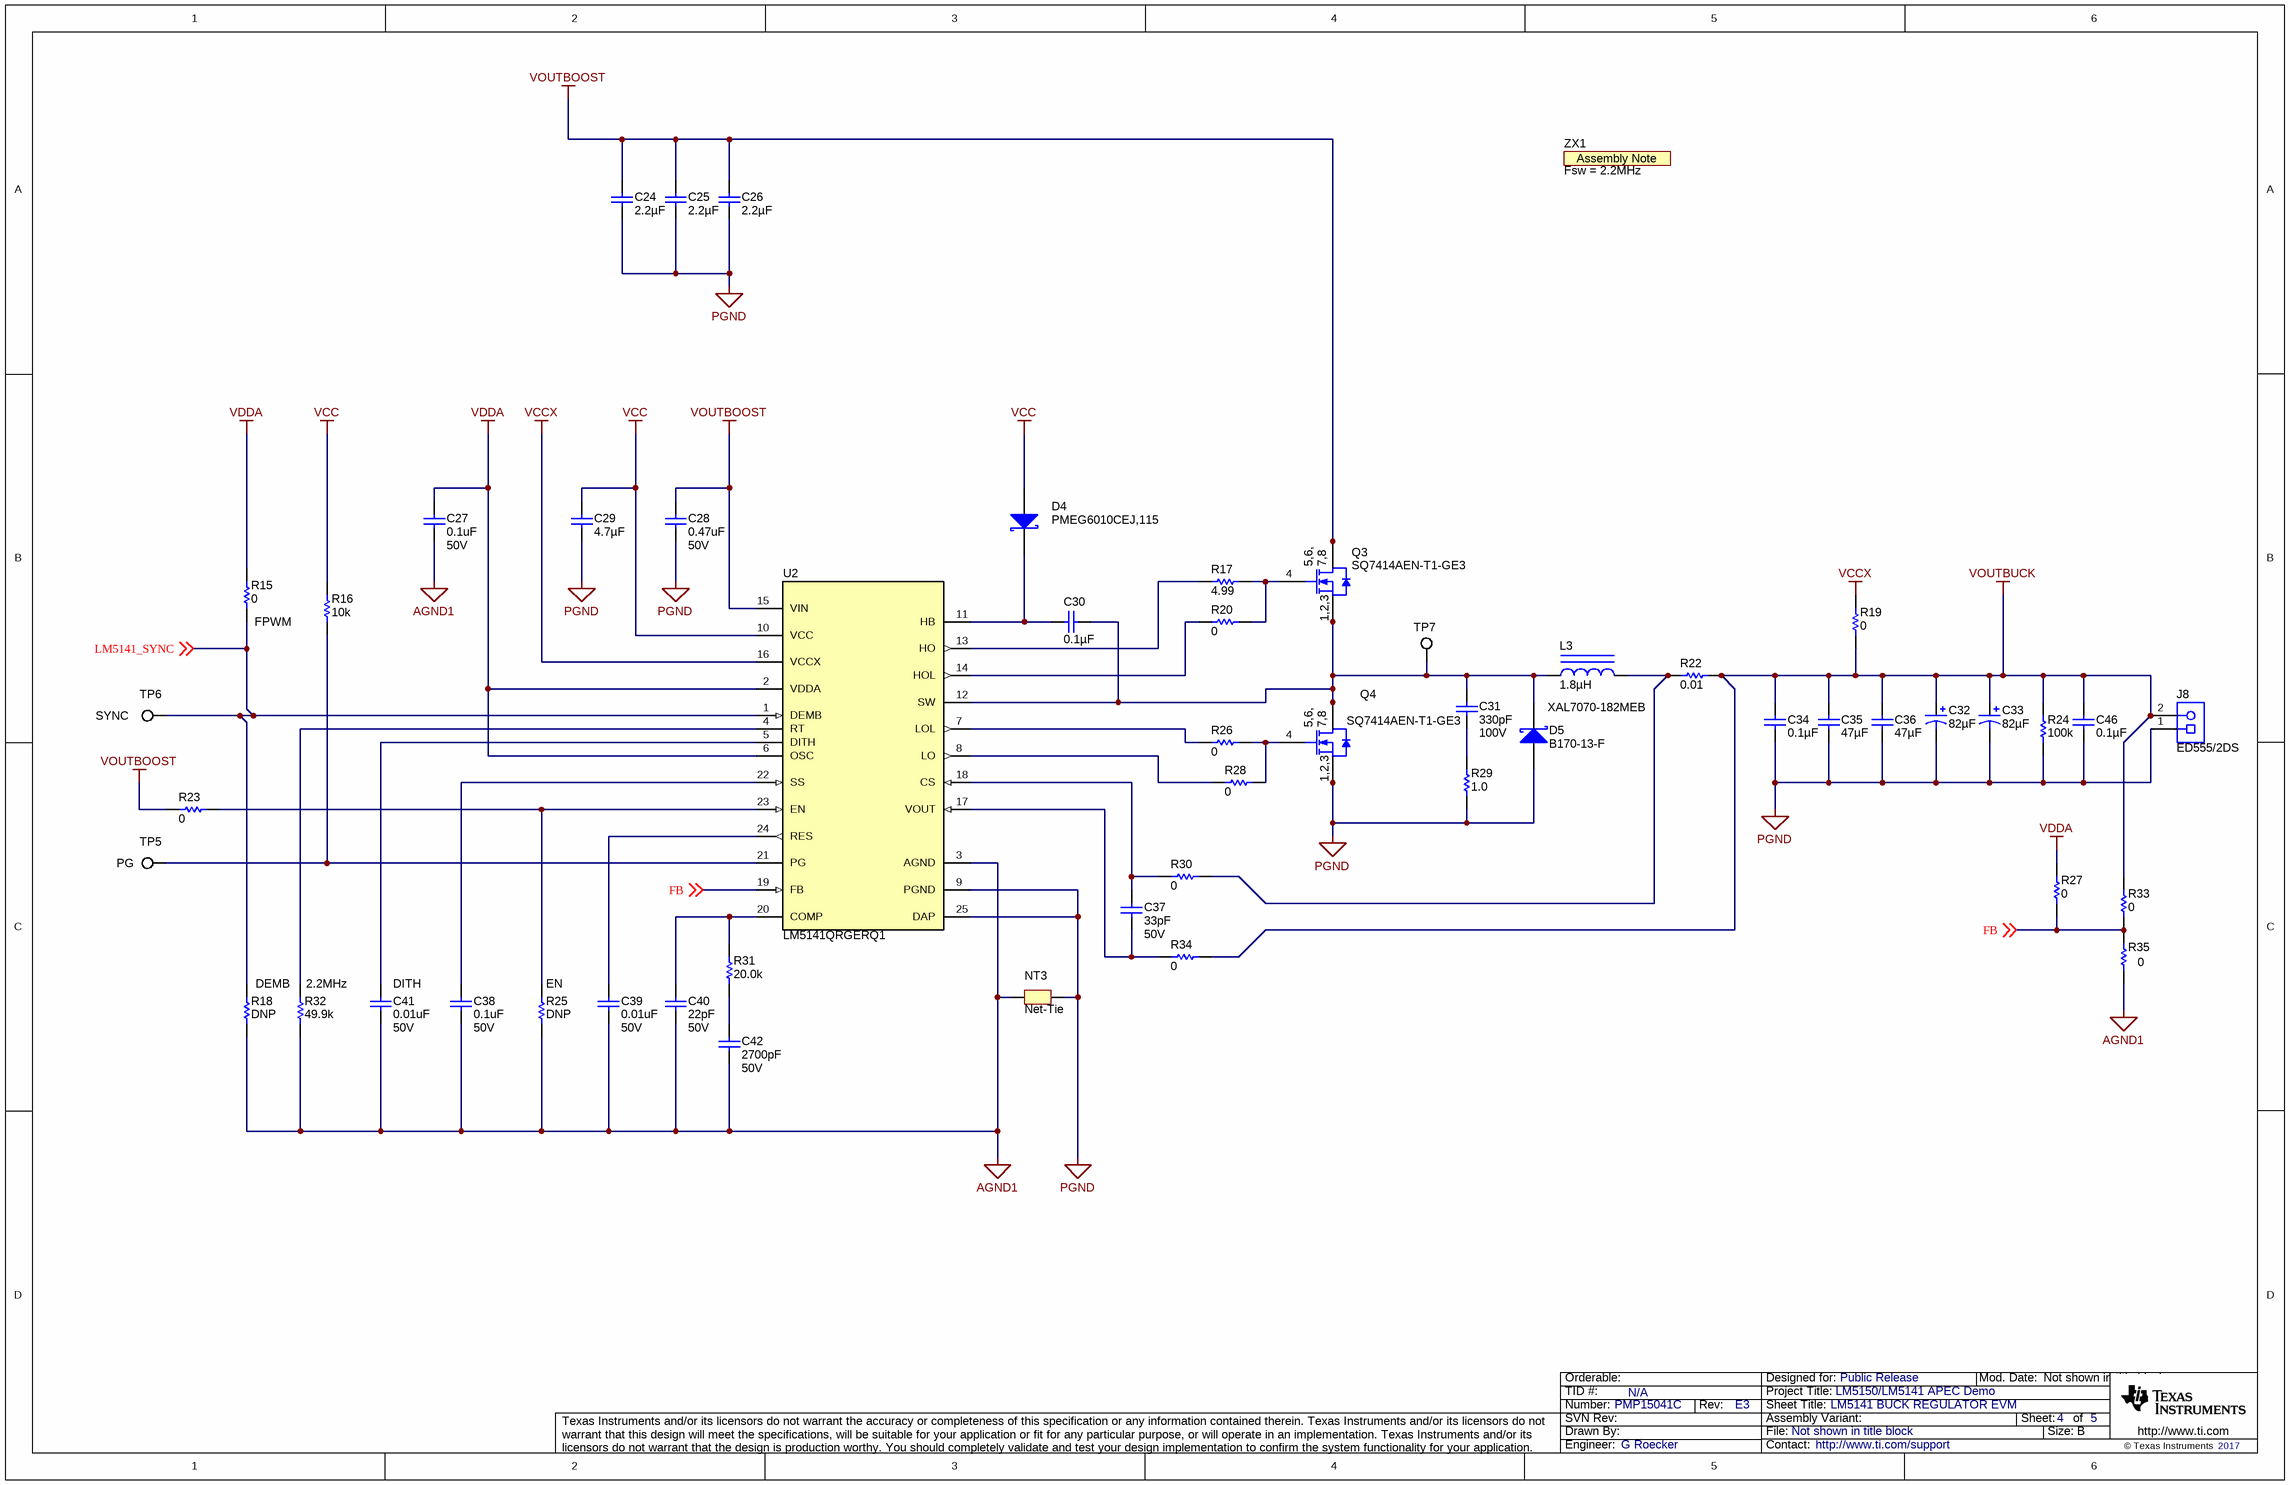
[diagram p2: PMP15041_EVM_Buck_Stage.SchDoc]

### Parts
C24  ValueDisplayed: 2.2µF  [1206_190]  (hidden comment: CL31B225KCHSNNE)
C25  ValueDisplayed: 2.2µF  [1206_190]  (hidden comment: CL31B225KCHSNNE)
C26  ValueDisplayed: 2.2µF  [1206_190]  (hidden comment: CL31B225KCHSNNE)
C27  ValueDisplayed: 0.1uF  VDC_V: 50V  [0402L]  (hidden comment: GCM155R71H104KE02D)
C28  ValueDisplayed: 0.47uF  VDC_V: 50V  [0603L]  (hidden comment: CGA3E3X7R1H474M080AE)
C29  ValueDisplayed: 4.7µF  [0603L]  (hidden comment: GRM188R61C475KAAJ)
C30  ValueDisplayed: 0.1µF  [0603L]  (hidden comment: C0603C104K5RACTU)
C31  ValueDisplayed: 330pF  VDC_V: 100V  [0402L]  (hidden comment: GRM155R72A331KA01D)
C32  ValueDisplayed: 82µF  [WCAP-PSLP_630x580]  (hidden comment: 875105344009)
C33  ValueDisplayed: 82µF  [WCAP-PSLP_630x580]  (hidden comment: 875105344009)
C34  ValueDisplayed: 0.1µF  [0603L]  (hidden comment: C0603C104K5RACTU)
C35  ValueDisplayed: 47µF  [1206]  (hidden comment: C3216X5R1C476M160AB)
C36  ValueDisplayed: 47µF  [1206]  (hidden comment: C3216X5R1C476M160AB)
C37  ValueDisplayed: 33pF  VDC_V: 50V  [0402L]  (hidden comment: C0402C330J5GAC)
C38  ValueDisplayed: 0.1uF  VDC_V: 50V  [0402L]  (hidden comment: GCM155R71H104KE02D)
C39  ValueDisplayed: 0.01uF  VDC_V: 50V  [0402L]  (hidden comment: CGA2B3X7R1H103K050BB)
C40  ValueDisplayed: 22pF  VDC_V: 50V  [0402L]  (hidden comment: GCM1555C1H220JA16D)
C41  ValueDisplayed: 0.01uF  VDC_V: 50V  [0402L]  (hidden comment: CGA2B3X7R1H103K050BB)
C42  ValueDisplayed: 2700pF  VDC_V: 50V  [0402L]  (hidden comment: GRM155R71H272KA01D)
C46  ValueDisplayed: 0.1µF  [0603L]  (hidden comment: C0603C104K5RACTU)
D4  PMEG6010CEJ,115  [SOD-323F]
D5  B170-13-F  [SMA]
J8  ED555/2DS  [TERM_BLK_ED555-2DS]
L3  ValueDisplayed: 1.8µH  [XAL7070]  (hidden comment: XAL7070-182MEB)
NT3  Net-Tie  [Net-Tie_10mil]  (net tie, no BOM)
Q3  SQ7414AEN-T1-GE3  [PowerPAK_1212-8_NoVias]
Q4  SQ7414AEN-T1-GE3  [PowerPAK_1212-8_NoVias]
R15  ValueDisplayed: 0  [0402L]  (hidden comment: MCR01MZPJ000)
R16  ValueDisplayed: 10k  [0402L]  (hidden comment: ERJ-2GEJ103X)
R17  ValueDisplayed: 4.99  [0402L]  (hidden comment: CRCW04024R99FKED)
R18  ValueDisplayed: DNP  [0402L]  (hidden comment: MCR01MZPJ000)
R19  ValueDisplayed: 0  [0603L]  (hidden comment: CRCW06030000Z0EA)
R20  ValueDisplayed: 0  [0402L]  (hidden comment: RK73Z1ETTP)
R22  ValueDisplayed: 0.01  [0612]  (hidden comment: PRL1632-R010-F-T1)
R23  ValueDisplayed: 0  [0402L]  (hidden comment: MCR01MZPJ000)
R24  ValueDisplayed: 100k  [0603L]  (hidden comment: CRCW0603100KFKEA)
R25  ValueDisplayed: DNP  [0402L]  (hidden comment: MCR01MZPJ000)
R26  ValueDisplayed: 0  [0402L]  (hidden comment: RK73Z1ETTP)
R27  ValueDisplayed: 0  [0402L]  (hidden comment: RK73Z1ETTP)
R28  ValueDisplayed: 0  [0402L]  (hidden comment: RK73Z1ETTP)
R29  ValueDisplayed: 1.0  [1206]  (hidden comment: CRM1206-JW-1R0ELF)
R30  ValueDisplayed: 0  [0402L]  (hidden comment: RK73Z1ETTP)
R31  ValueDisplayed: 20.0k  [0402L]  (hidden comment: CRCW040220K0FKED)
R32  ValueDisplayed: 49.9k  [0402L]  (hidden comment: ERJ-2RKF4992X)
R33  ValueDisplayed: 0  [0402L]  (hidden comment: RK73Z1ETTP)
R34  ValueDisplayed: 0  [0402L]  (hidden comment: RK73Z1ETTP)
R35  0  [0402L]
TP5  5002  [Keystone5002]  (value not drawn)
TP6  5002  [Keystone5002]  (value not drawn)
TP7  5015  [Testpoint_Keystone_Miniature]  (value not drawn)
U2  LM5141QRGERQ1  [RGE0024J]
ZX1  Fsw = 2.2MHz  [AssemblyNote]  (no BOM)

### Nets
AGND1: C27.1 C38.2 C39.2 C40.2 C41.2 C42.2 NT3.1 R18.2 R25.1 R32.1 R35.2 U2.3(AGND)
PGND: C24.2 C25.2 C26.2 C28.1 C29.1 C32.2(-) C33.2(-) C34.2 C35.2 C36.2 C46.2 D5.2(A) J8.1 NT3.2 Q4.1(S) Q4.2(S) Q4.3(S) R24.1 R29.1 U2.9(PGND) U2.25(DAP)
VCC: C29.2 D4.2(A) R16.1 U2.10(VCC)
VCCX: R19.1 U2.16(VCCX)
VDDA: C27.2 R15.2 R27.1 U2.2(VDDA) U2.6(OSC)
VOUTBOOST: C24.1 C25.1 C26.1 C28.2 Q3.5(D) Q3.6(D) Q3.7(D) Q3.8(D) Q3.9(D) R23.1 U2.15(VIN)
VOUTBUCK: C32.1(+) C33.1(+) C34.1 C35.1 C36.1 C46.1 J8.2 R19.2 R22.2 R24.2 R33.1 R34.2
FB: R27.2 R33.2 R35.1 U2.19(FB) ; off-sheet FB
LM5141_SYNC: R15.1 R18.1 TP6.1 U2.1(DEMB) ; off-sheet LM5141_SYNC
NetC30_1: C30.1 D4.1(K) U2.11(HB)
NetC30_2: C30.2 C31.1 D5.1(K) L3.1 Q3.1(S) Q3.2(S) Q3.3(S) Q4.5(D) Q4.6(D) Q4.7(D) Q4.8(D) Q4.9(D) TP7.1 U2.12(SW)
NetC31_2: C31.2 R29.2
NetC37_1: C37.1 R34.1 U2.17(VOUT)
NetC37_2: C37.2 R30.1 U2.18(CS)
NetC38_1: C38.1 U2.22(SS)
NetC39_1: C39.1 U2.24(RES)
NetC40_1: C40.1 R31.2 U2.20(COMP)
NetC41_1: C41.1 U2.5(DITH)
NetC42_1: C42.1 R31.1
NetL3_2: L3.2 R22.1 R30.2
NetQ3_4: Q3.4(G) R17.2 R20.1
NetQ4_4: Q4.4(G) R26.2 R28.1
NetR16_2: R16.2 TP5.1 U2.21(PG)
NetR17_1: R17.1 U2.13(HO)
NetR20_2: R20.2 U2.14(HOL)
NetR23_2: R23.2 R25.2 U2.23(EN)
NetR26_1: R26.1 U2.7(LOL)
NetR28_2: R28.2 U2.8(LO)
NetR32_2: R32.2 U2.4(RT)

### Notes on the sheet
- (near R15) FPWM
- (near TP6) SYNC
- (near TP5) PG
- DEMB
- (near R32) 2.2MHz
- (near C41) DITH
- (near R25) EN

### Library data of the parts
C24-C26 = CL31B225KCHSNNE: CAP, CERM, 2.2 µF, 100 V, +/- 10%, X7R, 1206_190; Manufacturer: Samsung Electro-Mechanics; Polarized: N; CompType: Capacitor; Value: 2.2uF; U/M: EA; Cap_F: 0.0000022; Tolerance_%: 10; Value1: Unknown; VDC_V: 100; Value2: 100V; TaMin_C: -55; TaMax_C: 125; Cap_Case: 1206
C27 = CMP-0006356-2: CAP, CERM, 0.1 uF, 50 V, +/- 10%, X7R, AEC-Q200 Grade 1, 0402; Manufacturer: MuRata; Polarized: N; Value: 0.1uF; U/M: EA; Cap_F: 100nF; Value1: Unknown; TaMin_C: -55°C; TaMax_C: 125°C; Cap_Case: 0402; SizeAreaWB_mm2: 3; SizeZ_mm: 0.6; SizeX_mm: 1; SizeY_mm: 0.5; AEC Qualified: Y; AEC Category: Q200
C28 = CMP-0007098-4: CAP, CERM, 0.47 uF, 50 V, +/- 20%, X7R, AEC-Q200 Grade 1, 0603; Manufacturer: TDK; Polarized: N; Value: 0.47uF; U/M: EA; Cap_F: 470nF; Value1: Unknown; TaMin_C: -55°C; TaMax_C: 125°C; Cap_Case: 0603; SizeAreaWB_mm2: 4.68; SizeZ_mm: 1; SizeX_mm: 1.6; SizeY_mm: 0.8; SizeArea_mm2: 1.28; AEC Qualified: Y; AEC Category: Q200
C29 = GRM188R61C475KAAJ: CAP, CERM, 4.7 µF, 16 V, +/- 10%, X5R, 0603; Manufacturer: MuRata; Polarized: N; CompType: Capacitor; Value: 4.7uF; U/M: EA; Cap_F: 0.0000047; Tolerance_%: 10; Value1: Unknown; VDC_V: 16; Value2: 16V; TaMin_C: -55; TaMax_C: 85; Cap_Case: 0603
C30 C34 C46 = C0603C104K5RACTU: CAP, CERM, 0.1 µF, 50 V, +/- 10%, X7R, 0603; Manufacturer: Kemet; Polarized: N; CompType: Capacitor; Value: 0.1uF; U/M: EA; Cap_F: 0.0000001; Tolerance_%: 10; Value1: Unknown; VDC_V: 50; Value2: 50V; TaMin_C: -55; TaMax_C: 125; Cap_Case: 0603
C31 = CMP-0006707-2: CAP, CERM, 330 pF, 100 V, +/- 10%, X7R, 0402; Manufacturer: MuRata; Polarized: N; CompType: Capacitor; Value: 330pF; U/M: EA; Value1: Unknown; TaMin_C: -55°C; TaMax_C: 125°C; Cap_Case: 0402; SizeAreaWB_mm2: 3; SizeZ_mm: 0.6; SizeX_mm: 1; SizeY_mm: 0.5; AEC Category: Q200
C32 C33 = 875105344009: CAP, Aluminum Polymer, 82 µF, 16 V, +/- 20%, 0.03 ohm, D6.3xL5.8mm SMD; Manufacturer: Wurth Elektronik; Polarized: Y; CompType: Capacitor; Value: 82uF; U/M: EA; Cap_F: 0.000082; Tolerance_%: 20; VDC_V: 16; Value2: 16V; ESR_ohm: 0.03; IRMS_A: 2.2; TaMin_C: -55; TaMax_C: 105; Cap_Case: 6.3x5.8mm
C35 C36 = C3216X5R1C476M160AB: CAP, CERM, 47 µF, 16 V, +/- 15%, X5R, 1206; Manufacturer: TDK; Polarized: N; CompType: Capacitor; Value: 47uF; U/M: EA; Cap_F: 0.000047; Tolerance_%: 15; Value1: Unknown; VDC_V: 16; Value2: 16V; TaMin_C: -55; TaMax_C: 85
C37 = CMP-0006242-2: CAP, CERM, 33 pF, 50 V, +/- 5%, C0G/NP0, 0402; Manufacturer: Kemet; Polarized: N; Value: 33pF; U/M: EA; Value1: Unknown; TaMin_C: -55°C; TaMax_C: 125°C; Cap_Case: 0402; SizeAreaWB_mm2: 3; SizeZ_mm: 0.6; SizeX_mm: 1; SizeY_mm: 0.5; AEC Category: Q200
C38 = CMP-0006356-2: CAP, CERM, 0.1 uF, 50 V, +/- 10%, X7R, AEC-Q200 Grade 1, 0402; Manufacturer: MuRata; Polarized: N; CompType: Capacitor; Value: 0.1uF; U/M: EA; Cap_F: 100nF; Value1: Unknown; TaMin_C: -55°C; TaMax_C: 125°C; Cap_Case: 0402; SizeAreaWB_mm2: 3; SizeZ_mm: 0.6; SizeX_mm: 1; SizeY_mm: 0.5; AEC Qualified: Y; AEC Category: Q200
C39 = CMP-0006324-2: CAP, CERM, 0.01 uF, 50 V, +/- 10%, X7R, AEC-Q200 Grade 1, 0402; Manufacturer: TDK; Polarized: N; Value: 0.01uF; U/M: EA; Cap_F: 10nF; ESR_ohm: 3.33065d; Value1: 0.333065 ohm; IRMS_A: 3.23373dA; TaMin_C: -55°C; TaMax_C: 125°C; Cap_Case: 0402; SizeAreaWB_mm2: 3; SizeZ_mm: 0.6; SizeX_mm: 1; SizeY_mm: 0.5; AEC Qualified: Y; AEC Category: Q200
C40 = CMP-0006348-2: CAP, CERM, 22 pF, 50 V, +/- 5%, C0G/NP0, AEC-Q200 Grade 1, 0402; Manufacturer: MuRata; Polarized: N; Value: 22pF; U/M: EA; Value1: Unknown; TaMin_C: -55°C; TaMax_C: 125°C; Cap_Case: 0402; SizeAreaWB_mm2: 3; SizeZ_mm: 0.6; SizeX_mm: 1; SizeY_mm: 0.5; AEC Qualified: Y; AEC Category: Q200
C41 = CMP-0006324-2: CAP, CERM, 0.01 uF, 50 V, +/- 10%, X7R, AEC-Q200 Grade 1, 0402; Manufacturer: TDK; Polarized: N; CompType: Capacitor; Value: 0.01uF; U/M: EA; Cap_F: 10nF; ESR_ohm: 3.33065d; Value1: 0.333065 ohm; IRMS_A: 3.23373dA; TaMin_C: -55°C; TaMax_C: 125°C; Cap_Case: 0402; SizeAreaWB_mm2: 3; SizeZ_mm: 0.6; SizeX_mm: 1; SizeY_mm: 0.5; AEC Qualified: Y; AEC Category: Q200
C42 = CMP-0006686-2: CAP, CERM, 2700 pF, 50 V, +/- 10%, X7R, 0402; Manufacturer: MuRata; Polarized: N; CompType: Capacitor; Value: 2700pF; U/M: EA; Cap_F: 2.7nF; Value1: Unknown; TaMin_C: -55°C; TaMax_C: 125°C; Cap_Case: 0402; SizeAreaWB_mm2: 3; SizeZ_mm: 0.6; SizeX_mm: 1; SizeY_mm: 0.5; AEC Category: Q200
D4 = PMEG6010CEJ,115: Diode, Schottky, 60 V, 1 A, SOD-323F; Manufacturer: NXP Semiconductor; U/M: EA; Vf_V: 0.66; Value: 60V; Value1: 1A; Value2: 0.66V; Io_A: 1; Vr_V: 60; TJmax_C: 150
D5 = B170-13-F: Diode, Schottky, 70 V, 1 A, SMA; Manufacturer: Diodes Inc.; U/M: EA; Vf_V: 0.79; Value: 70V; Value1: 1A; Value2: 0.79V; Io_A: 1; Vr_V: 70; TJmax_C: 150; RJC_CperW: 25
J8 = CMP-0074913-1: as J7 on sheet PMP15041_EVM_Boost_Stage
L3 = XAL7070-182MEB: Inductor, Shielded, Composite, 1.8 µH, 21 A, 0.00405 ohm, SMD; Manufacturer: Coilcraft; Value: 1.8uH; Ind_H: 1.8E-6; Imax_A: 21; Irms: 21A @ 40C rise; Isat: 25A @ 30% inductance drop; Value2: 21A; SizeAreaWB_mm2: 87.4; SizeArea_mm2: 54; SizeX_mm: 7.2; SizeY_mm: 7.5; SizeZ_mm: 7; AEC Category: Q200
NT3 = Net-Tie: as NT1 on sheet PMP15041_EVM_Boost_Stage
Q3 Q4 = SQ7414AEN-T1-GE3: MOSFET N-CH 60V 5.6A PPAK 1212-8; Manufacturer: Vishay Siliconix; CompType: Used in some BOM reports.  Useful for finding later.; U/M: EA; SymbolCreator: a0413446; Rds On (Max) @ Id, Vgs: 26 mOhm @ 5.7A, 10V; Power - Max: 62W; Input Capacitance (Ciss) @ Vds: 980pF @ 30V; Vgs(th) (Max) @ Id: 2.5V @ 250µA; FET Feature: Standard; Gate Charge (Qg) @ Vgs: 24nC @ 10V; Current - Continuous Drain (Id) @ 25°C: 16A (Tc); FET Type: MOSFET N-Channel, Metal Oxide
R15 = CMP-0027002-2: RES, 0, 5%, 0.063 W, 0402; Manufacturer: Rohm; Value: 0; Value_Code: 0000; Power_W: 63mW; Value2: 0.063W; VDC_V: 50V; TempCo: 500 ppm/C; EIA_Code: E24; U/M: EA; SizeX_mm: 1; SizeY_mm: 0.5; SizeZ_mm: 0.6; AEC Category: Q200
R16 = CMP-0026994-4: RES, 10 k, 5%, 0.1 W, AEC-Q200 Grade 0, 0402; Manufacturer: Panasonic; CompType: Resistor; Value: 10k; Value_Code: 10k0; Power_W: 100mW; Value2: 0.1W; VDC_V: 50V; TempCo: 200 ppm/C; EIA_Code: E24; U/M: EA; SizeX_mm: 1; SizeY_mm: 0.5; SizeZ_mm: 0.6; AEC Qualified: Y; AEC Grade: 0; AEC Category: Q200
R17 = CMP-0026434-2: RES, 4.99, 1%, 0.063 W, AEC-Q200 Grade 0, 0402; Manufacturer: Vishay-Dale; CompType: Resistor; Value: 4.99; Value_Code: 4R99; Power_W: 63mW; Value2: 0.063W; VDC_V: 50V; TempCo: 100 ppm/C; EIA_Code: E96; SizeX_mm: 1; SizeY_mm: 0.5; SizeZ_mm: 0.6; AEC Qualified: Y; AEC Category: Q200; AEC Grade: 0
R18 R23 R25 = CMP-0027002-2: RES, 0, 5%, 0.063 W, 0402; Manufacturer: Rohm; CompType: Resistor; Value: 0; Value_Code: 0000; Power_W: 63mW; Value2: 0.063W; VDC_V: 50V; TempCo: 500 ppm/C; EIA_Code: E24; U/M: EA; SizeX_mm: 1; SizeY_mm: 0.5; SizeZ_mm: 0.6; AEC Category: Q200
R19 = CRCW06030000Z0EA: RES, 0, 5%, 0.1 W, 0603; Manufacturer: Vishay-Dale; CompType: Resistor; Value: 0; Value_Code: 0000; Tolerance_%: 5; Power_W: 0.1; Value2: 0.1W; VDC_V: 75; TempCo: 200 ppm/C; EIA_Code: E24; U/M: EA
R20 R30 R33 R34 = CMP-0027007-2: RES, 0, 5%, 0.063 W, AEC-Q200 Grade 0, 0402; Manufacturer: KOA Speer; CompType: Resistor; Value: 0; Value_Code: 0000; Power_W: 63mW; Value2: 0.063W; TempCo: ppm/C; EIA_Code: E24; U/M: EA; SizeX_mm: 1; SizeY_mm: 0.5; SizeZ_mm: 0.6; AEC Qualified: Y; AEC Category: Q200
R22 = PRL1632-R010-F-T1: RES, 0.01, 1%, 1 W, 0612; Manufacturer: Susumu Co Ltd; CompType: Resistor; Value: 0.01; Value_Code: R010; Tolerance_%: 1; Value2: 1W; TempCo: 200 ppm/C; EIA_Code: E96; U/M: EA; SizeArea_mm2: 5.12; SizeAreaWB_mm2: 10.92; SizeX_mm: 1.6; SizeY_mm: 3.2; SizeZ_mm: 0.85; AEC Category: Q200
R24 = CRCW0603100KFKEA: RES, 100 k, 1%, 0.1 W, 0603; Manufacturer: Vishay-Dale; CompType: Resistor; Value: 100k; Res_ohm: 100000; Tolerance_%: 1; Power_W: 0.1; Value2: 0.1W; VDC_V: 75; TempCo: 100 ppm/C; EIA_Code: E96; U/M: EA
R26-R28 = CMP-0027007-2: RES, 0, 5%, 0.063 W, AEC-Q200 Grade 0, 0402; Manufacturer: KOA Speer; Value: 0; Value_Code: 0000; Power_W: 63mW; Value2: 0.063W; TempCo: ppm/C; EIA_Code: E24; U/M: EA; SizeX_mm: 1; SizeY_mm: 0.5; SizeZ_mm: 0.6; AEC Qualified: Y; AEC Category: Q200
R29 = CRM1206-JW-1R0ELF: RES, 1.0, 5%, 0.5 W, 1206; Manufacturer: Bourns; CompType: Resistor; Value: 1.0; Res_ohm: 1; Value_Code: 1R00; Tolerance_%: 5; Power_W: 0.5; Value2: 0.5W; TempCo: 150 ppm/C; EIA_Code: E24; U/M: EA
R31 = CMP-0026162-2: RES, 20.0 k, 1%, 0.063 W, AEC-Q200 Grade 0, 0402; Manufacturer: Vishay-Dale; CompType: Resistor; Value: 20.0k; Res_ohm: 20k; Value_Code: 20k0; Power_W: 63mW; Value2: 0.063W; VDC_V: 50V; TempCo: 100 ppm/C; EIA_Code: E96; SizeX_mm: 1; SizeY_mm: 0.5; SizeZ_mm: 0.6; AEC Qualified: Y; AEC Category: Q200; AEC Grade: 0
R32 = CMP-0026702-1: RES, 49.9 k, 1%, 0.1 W, AEC-Q200 Grade 0, 0402; Manufacturer: Panasonic; Value: 49.9k; Value_Code: 49k9; Power_W: 100mW; Value2: 0.1W; VDC_V: 50V; TempCo: 100 ppm/C; EIA_Code: E96; U/M: EA; AEC Category: Q200; AEC Qualified: Y; AEC Grade: 0; SizeArea_mm2: 0.5; SizeX_mm: 1; SizeZ_mm: 0.6
R35 = CMP-0027007-2: RES, 0, 5%, 0.063 W, AEC-Q200 Grade 0, 0402; PartNumber: RK73Z1ETTP; Manufacturer: KOA Speer; CompType: Resistor; Value_Code: 0000; Power_W: 63mW; Value2: 0.063W; TempCo: ppm/C; EIA_Code: E24; U/M: EA; SizeX_mm: 1; SizeY_mm: 0.5; SizeZ_mm: 0.6; AEC Qualified: Y; AEC Category: Q200
TP5 TP6 = 5002: Test Point, Miniature, White, TH; Manufacturer: Keystone; CompType: Test Point Loop; U/M: EA
TP7 = 5015: as TP1 on sheet PMP15041_EVM_Boost_Stage
U2 = LM5141QRGERQ1: Wide Input 2.2MHz low Iq Synchronous Buck Controller, RGE0024J (VQFN-24); Manufacturer: Texas Instruments; SymbolCreator: Altium; SizeArea_mm2: 16; SizeAreaWB_mm2: 25; SizeX_mm: 4; SizeZ_mm: 1; CompType: IC; U/M: EA
ZX1 = AssemblyNote: This Assembly Note will show in the PcbDoc and associated outputs; SymbolCreator: codlsc

## Sheet PMP15041_SYNC_Stage.SchDoc
size 431 x 279 mm; Date: Not shown in title block; ApprovedBy: Not shown in title block; CheckedBy: Not shown in title block; Author: Not shown in title block; CompanyName: Not shown in title block; Engineer: Not shown in title block; Organization: Not shown in title block; Address1: Not shown in title block; Address2: Not shown in title block; Address3: Not shown in title block; Address4: Not shown in title block; DocumentNumber: 5; Revision: Use project parameter SCH_Rev; SheetNumber: 5; SheetTotal: 5; PageSetup: Record=PageOptions¦CenterHorizontal=True¦CenterVertical=True¦PrintScale=1.00¦XCorrection=1.00¦YCorrection=1.00¦PrintKind=0¦BorderSize=5000000¦LeftOffset=0¦BottomOffset=0¦Orientation=2¦PaperLength=1000¦PaperWidth=1000¦Scale=100¦PaperSource=15¦PrintQuality=600¦MediaType=1¦DitherType=10¦PaperKind=Letter¦PrintScaleMode=1
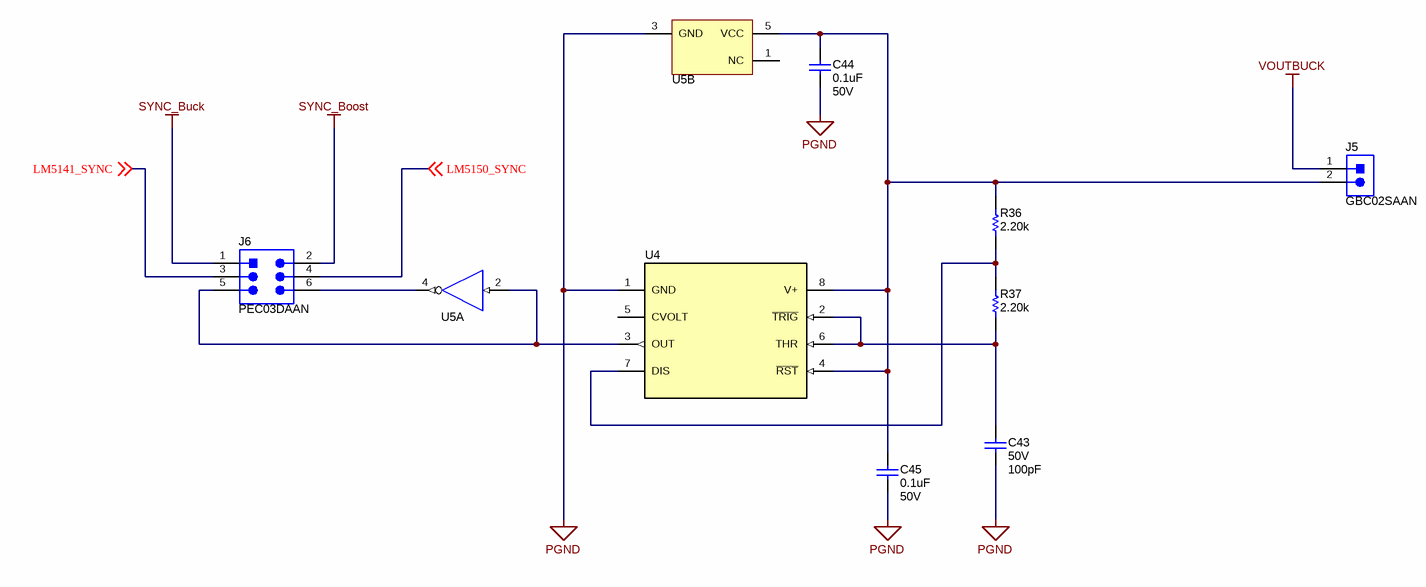
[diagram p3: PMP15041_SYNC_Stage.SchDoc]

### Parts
C43  VDC_V: 50V  ValueDisplayed: 100pF  [0603L]  (hidden comment: 885012006057)
C44  ValueDisplayed: 0.1uF  VDC_V: 50V  [0402L]  (hidden comment: GCM155R71H104KE02D)
C45  ValueDisplayed: 0.1uF  VDC_V: 50V  [0402L]  (hidden comment: GCM155R71H104KE02D)
J5  GBC02SAAN  [Sullins_Gxx02SAAN]
J6  PEC03DAAN  [SULLINS_PEC03DAAN]
R36  ValueDisplayed: 2.20k  [0603L]  (hidden comment: RC0603FR-072K2L)
R37  ValueDisplayed: 2.20k  [0603L]  (hidden comment: RC0603FR-072K2L)
U4  LMC555CMMX  [DGK0008A_N]  (value not drawn)
U5  SN74LVC1G04DBVR  [DBV0005A_N]  (value not drawn)  (parts A,B of 2)

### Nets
PGND: C43.2 C44.1 C45.1 U4.1(GND) U5.3(GND)
SYNC_Boost: J6.2
SYNC_Buck: J6.1
VOUTBUCK: J5.1
LM5141_SYNC: J6.3 ; off-sheet LM5141_SYNC
LM5150_SYNC: J6.4 ; off-sheet LM5150_SYNC
NetC43_1: C43.1 R37.1 U4.2(~{TRIG}) U4.6(THR)
NetC44_2: C44.2 C45.2 J5.2 R36.2 U4.4(~{RST}) U4.8(V+) U5.5(VCC)
NetJ6_5: J6.5 U4.3(OUT) U5.2(A)
NetJ6_6: J6.6 U5.4(Y)
NetR36_1: R36.1 R37.2 U4.7(DIS)

Not connected (* = marked no-connect by the designer): U4 5(CVOLT); U5 1(NC)

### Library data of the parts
C43 = CMP-0006822-4: CAP, CERM, 100 pF, 50 V, +/- 5%, C0G/NP0, 0603; Manufacturer: Wurth Elektronik; TaMin_C: -55°C; Polarized: N; SizeAreaWB_mm2: 4.68; Value1: Unknown; U/M: EA; Value: 100pF; TaMax_C: 125°C; SizeZ_mm: 1; SizeX_mm: 1.6; SizeY_mm: 0.8; Cap_Case: 0603; SizeArea_mm2: 1.28; AEC Category: Q200
C44 C45 = CMP-0006356-2: as C27 on sheet PMP15041_EVM_Buck_Stage
J5 = CMP-0054576-1: Header, 2.54 mm, 2x1, Gold, TH; Manufacturer: Sullins Connector Solutions; CT: FALSE; CNHeader: TRUE
J6 = CMP-0054552-1: Header, 100mil, 3x2, Tin, TH; Manufacturer: Sullins Connector Solutions; CNHeader: TRUE; Green_Lifecycle: Not Set; Green_REACh: Incomplete; CT: FALSE; Cert_UL: Y; Current_A: 3A; Gender: Male; Pitch_mm: 2.54; Row_Count: 2; Shrouded: N; Voltage_V: 1.8kV
R36 R37 = CMP-0022986-3: RES, 2.20 k, 1%, 0.1 W, 0603; Manufacturer: Yageo America; Power_W: 100mW; TempCo: 200 ppm/C; Value_Code: 2k20; U/M: EA; Value: 2.20k; Res_ohm: 2.2k; SizeX_mm: 1.6; SizeY_mm: 0.8; SizeZ_mm: 1; Value2: 0.1W; SizeArea_mm2: 1.28; VDC_V: 150V; AEC Category: Q200
U4 = CMP-0068899-1: CMOS Timer, 8-pin Mini SOIC; Manufacturer: Texas Instruments; CompType: Analog IC; PowerWise: N; PackageTopMarking: ZXTT*ZC5
U5 = CMP-0051683-1: Single Inverter, DBV0005A, LARGE T&R; Manufacturer: Texas Instruments; 3-State Output: No; Sub-Family: Inverting Buffer/Driver; Logic: Inverting; Rating: Catalog; VCC(Max)(V): 5.5; ICC @ Nom Voltage(Max)(mA): 0.01; Output Type: CMOS; Output Drive (IOL/IOH)(Max)(mA): 32/-32; tpd @ Nom Voltage(Max)(ns): 7.5,5.2,4.2,3.7; Technology Family: LVC; Input Type: CMOS/TTL; Bits(#): 1; F @ Nom Voltage(Max)(Mhz): 150; VCC(Min)(V): 1.65; Voltage(Nom)(V): 1.8,2.5,3.3,5

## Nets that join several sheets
PGND: PMP15041_EVM_Boost_Stage (18 pins), PMP15041_EVM_Buck_Stage (21 pins), PMP15041_SYNC_Stage (5 pins)
VOUTBOOST: PMP15041_EVM_Boost_Stage (15 pins), PMP15041_EVM_Buck_Stage (11 pins)
VOUTBUCK: PMP15041_EVM_Buck_Stage (12 pins), PMP15041_SYNC_Stage (J5.1)
LM5141_SYNC: PMP15041_EVM_Buck_Stage (R15.1 R18.1 TP6.1 U2.1), PMP15041_SYNC_Stage (J6.3)
LM5150_SYNC: PMP15041_EVM_Boost_Stage (U1.1), PMP15041_SYNC_Stage (J6.4)

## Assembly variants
001: not fitted C37 C43 C44 C45 FID1 FID2 FID3 R18 R25 R27 R33 R36 R37 U4 U5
